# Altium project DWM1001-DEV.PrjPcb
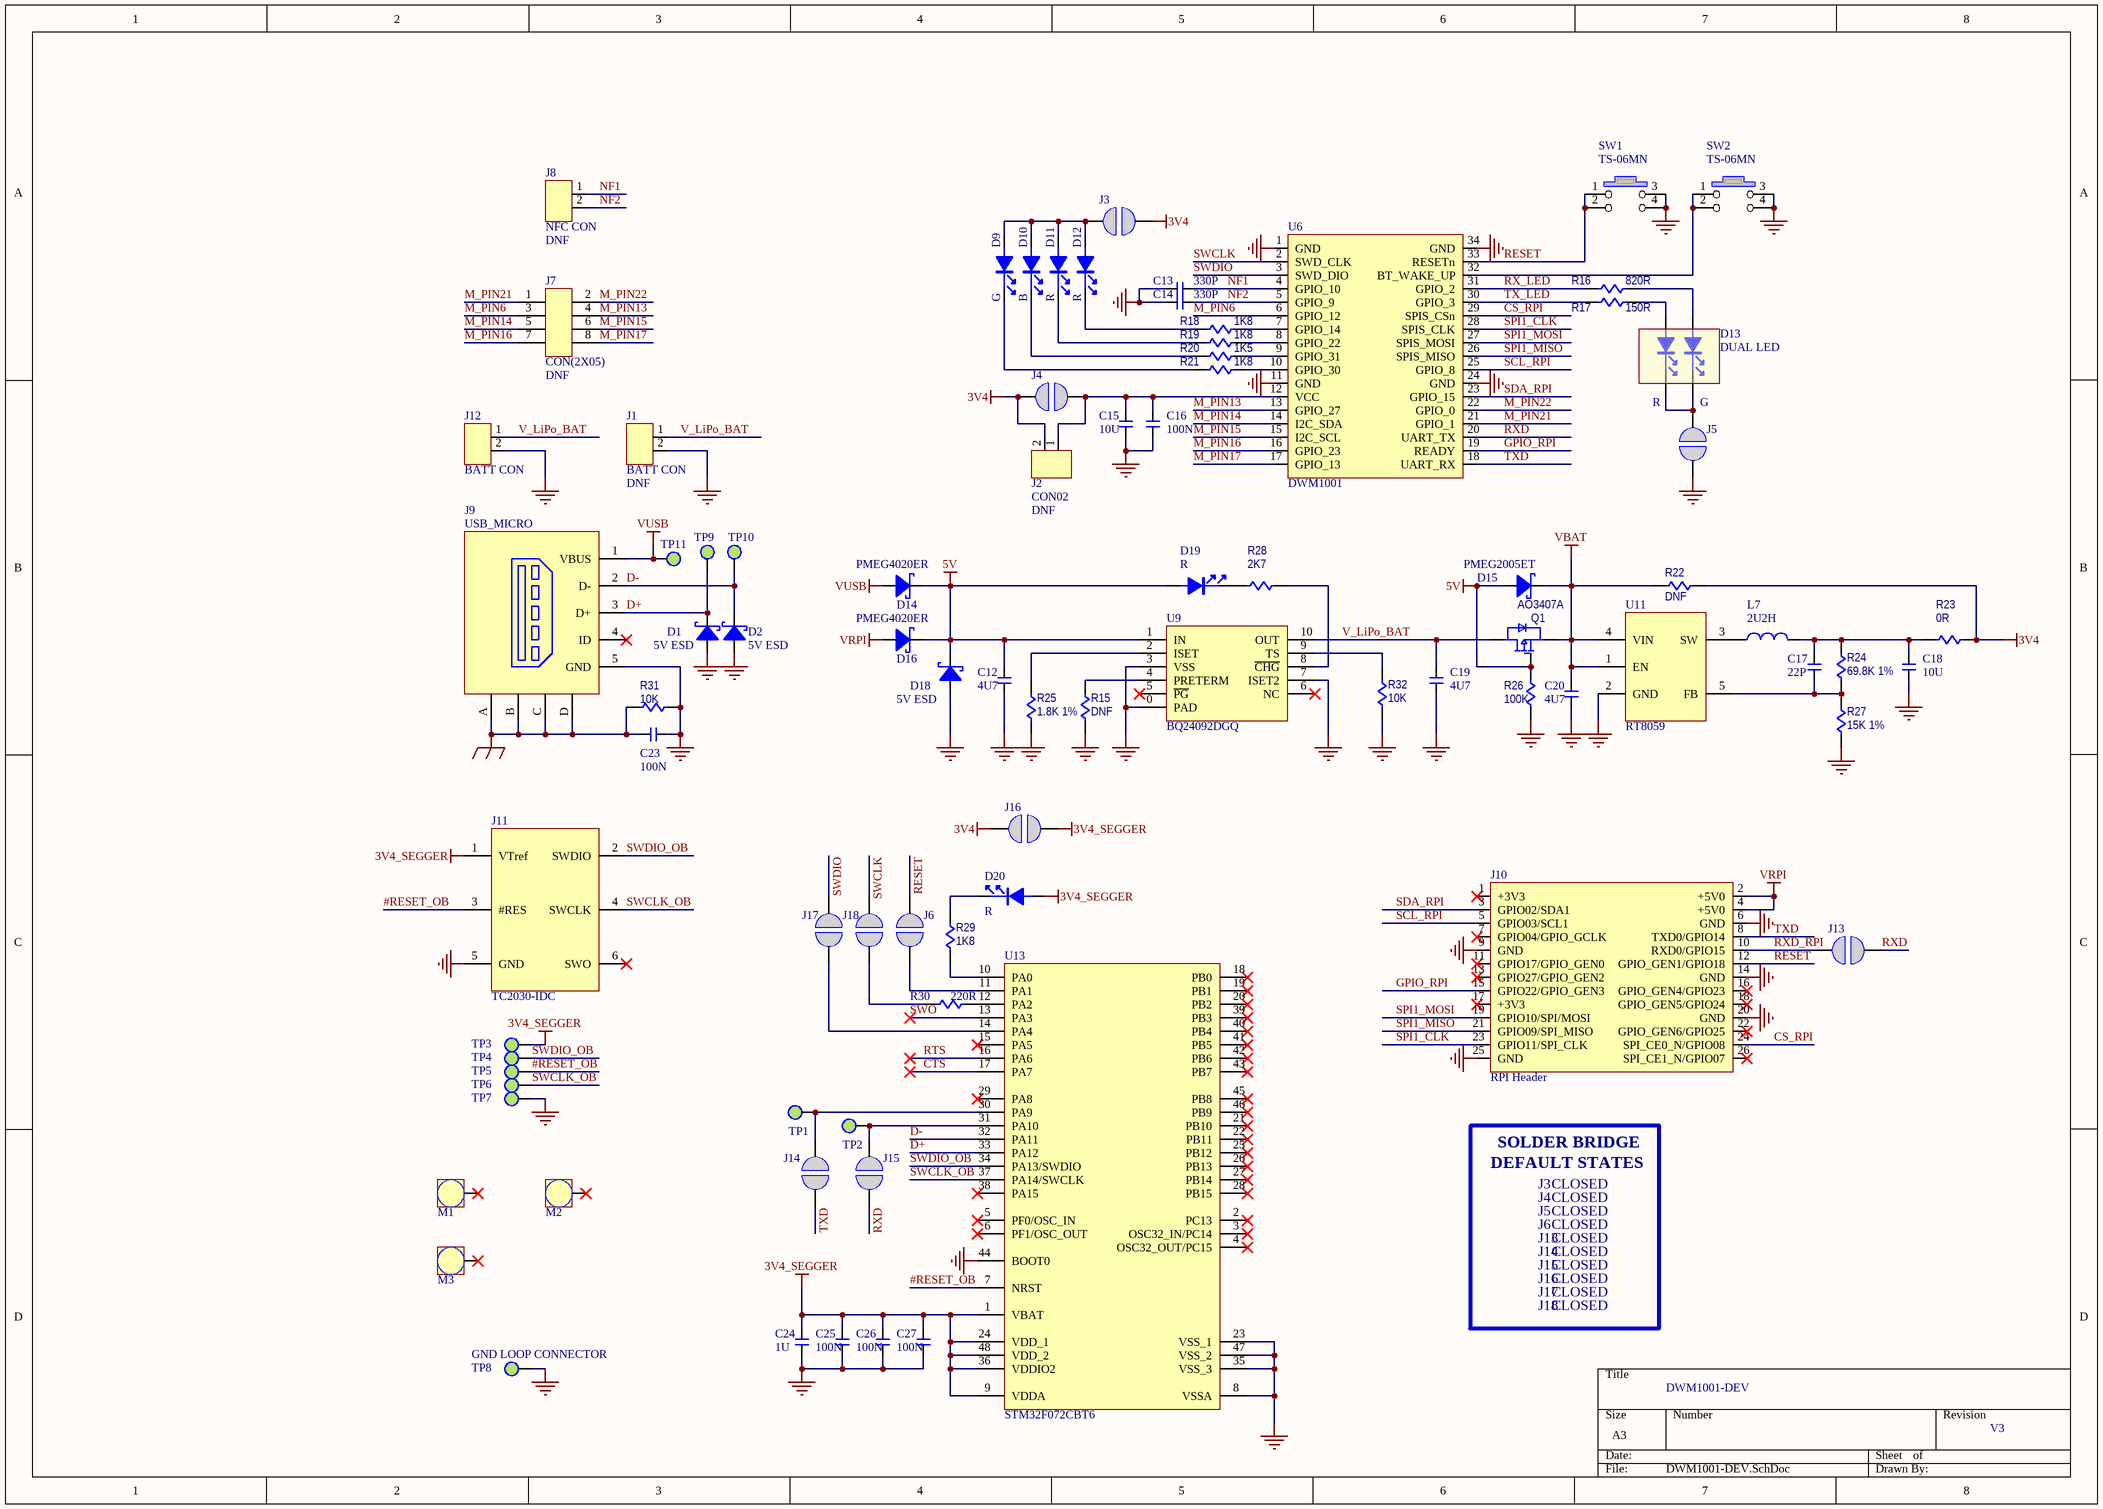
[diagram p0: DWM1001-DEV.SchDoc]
1 sheet, 85 parts. Net scope: global (net labels, ports and power ports of the same name join across sheets).
Board file: DWM1001-DEV.PcbDoc

## Sheet DWM1001-DEV.SchDoc
size A3

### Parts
C12  4U7  [C-SMT-0603]
C13  330P  [C-SMT-0402]
C14  330P  [C-SMT-0402]
C15  10U  [C-SMT-0603]
C16  100N  [C-SMT-0402]
C17  22P  [C-SMT-0402]
C18  10U  [C-SMT-0603]
C19  4U7  [C-SMT-0603]
C20  4U7  [C-SMT-0603]
C23  100N  [C-SMT-0402]
C24  1U  [C-SMT-0402]
C25  100N  [C-SMT-0402]
C26  100N  [C-SMT-0402]
C27  100N  [C-SMT-0402]
D1  5V ESD  [C-SMT-0603]
D2  5V ESD  [C-SMT-0603]
D9  G  [LED-SMT-0603]
D10  B  [LED-SMT-0603]
D11  R  [LED-SMT-0603]
D12  R  [LED-SMT-0603]
D13  DUAL LED  [LED_DUAL]
D14  PMEG4020ER  [DIO_SOD123]
D15  PMEG2005ET  [DIO_SOT23]
D16  PMEG4020ER  [DIO_SOD123]
D18  5V ESD  [C-SMT-0603]
D19  R  [LED-SMT-0603]
D20  R  [LED-SMT-0603]
J1  BATT CON  [CON-100MIL-02]
J2  CON02  [CON-100MIL-02]
J3  SHORT  [PAD_JUMPER]  (value not drawn)
J4  SHORT  [PAD_JUMPER]  (value not drawn)
J5  SHORT  [PAD_JUMPER]  (value not drawn)
J6  SHORT  [PAD_JUMPER]  (value not drawn)
J7  CON(2X05)  [CON-100MIL-2X04]
J8  NFC CON  [CON-100MIL-02]
J9  USB_MICRO  [USB_MICRO_U6F05E-CXT2-B15]
J10  RPI Header  [CON-100MIL-2X13]
J11  TC2030-IDC  [JLINK_6PIN_ADAPTOR]
J12  BATT CON  [SH02AYS]
J13  SHORT  [PAD_JUMPER]  (value not drawn)
J14  SHORT  [PAD_JUMPER]  (value not drawn)
J15  SHORT  [PAD_JUMPER]  (value not drawn)
J16  SHORT  [PAD_JUMPER]  (value not drawn)
J17  SHORT  [PAD_JUMPER]  (value not drawn)
J18  SHORT  [PAD_JUMPER]  (value not drawn)
L7  2U2H  [IND_SDB3015]
M1  mt_hole  [MT_hole_3mm - NPTH]  (value not drawn)
M2  mt_hole  [MT_hole_3mm - NPTH]  (value not drawn)
M3  mt_hole  [MT_hole_3mm - NPTH]  (value not drawn)
Q1  AO3407A  [FET_SOT23_GSD]
R15  DNF  [R-SMT-0402]
R16  820R  [R-SMT-0402]
R17  150R  [R-SMT-0402]
R18  1K8  [R-SMT-0402]
R19  1K8  [R-SMT-0402]
R20  1K5  [R-SMT-0402]
R21  1K8  [R-SMT-0402]
R22  DNF  [R-SMT-0402]
R23  0R  [R-SMT-0402]
R24  69.8K 1%  [R-SMT-0402]
R25  1.8K 1%  [R-SMT-0402]
R26  100K  [R-SMT-0402]
R27  15K 1%  [R-SMT-0402]
R28  2K7  [R-SMT-0402]
R29  1K8  [R-SMT-0402]
R30  220R  [R-SMT-0402]
R31  10K  [R-SMT-0402]
R32  10K  [R-SMT-0402]
SW1  TS-06MN  [TS-1143S]
SW2  TS-06MN  [TS-1143S]
TP1  TXD  [PAD/R40MIL-SMD]  (value not drawn)
TP2  RXD  [PAD/R40MIL-SMD]  (value not drawn)
TP3  3V4_SEGGER  [PAD/R40MIL-SMD]  (value not drawn)
TP4  SWDIO_OB  [PAD/R40MIL-SMD]  (value not drawn)
TP5  #RESET_OB  [PAD/R40MIL-SMD]  (value not drawn)
TP6  SWCLK_OB  [PAD/R40MIL-SMD]  (value not drawn)
TP7  GND  [PAD/R40MIL-SMD]  (value not drawn)
TP8  GND LOOP CONNECTOR  [TP_LOOP_CONNECTOR]
TP9  D+  [PAD/R40MIL-SMD]  (value not drawn)
TP10  D-  [PAD/R40MIL-SMD]  (value not drawn)
TP11  VUSB  [PAD/R40MIL-SMD]  (value not drawn)
U6  DWM1001  [LM1_E1]
U9  BQ24092DGQ  [IC_MSOP10 - TI - DGQ]
U11  RT8059  [SOT23-5]
U13  STM32F072CBT6

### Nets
3V4: J2.2 J3.1 J4.1 J16.1 R22.2 R23.2
3V4_SEGGER: C24.1 C25.1 C26.1 C27.1 D20.A J11.1(VTref) J16.2 TP3.1 U13.1(VBAT) U13.9(VDDA) U13.24(VDD_1) U13.36(VDDIO2) U13.48(VDD_2)
5V: C12.1 D14.2(K) D15.1(A) D16.2(K) D18.2(K) D19.A Q1.G R26.2 U9.1(IN)
EARTH: C23.1 J9.A J9.B J9.C J9.D R31.1
GND: C12.2 C13.1 C14.1 C15.2 C16.2 C18.2 C19.2 C20.2 C23.2 C24.2 C25.2 C26.2 C27.2 D1.1(A) D2.1(A) D18.1(A) J1.2 J5.1 J9.5(GND) J10.6(GND) J10.9(GND) J10.14(GND) J10.20(GND) J10.25(GND) J11.5(GND) J12.2 R15.1 R25.1 R26.1 R27.1 R31.2 R32.1 SW1.3 SW1.4 SW2.3 SW2.4 TP7.1 TP8.1 U6.1(GND) U6.11(GND) U6.24(GND) U6.34(GND) U9.0(PAD) U9.3(VSS) U9.7(ISET2) U11.2(GND) U13.8(VSSA) U13.23(VSS_1) U13.35(VSS_3) U13.44(BOOT0) U13.47(VSS_2)
VBAT: C20.1 D15.2(K) Q1.S R22.1 U11.1(EN) U11.4(VIN)
VRPI: D16.1(A) J10.2(+5V0) J10.4(+5V0)
VUSB: D14.1(A) J9.1(VBUS) TP11.1
#RESET_OB: J11.3(#RES) TP5.1 U13.7(NRST)
CS_RPI: J10.24(SPI_CE0_N/GPIO08) U6.29(SPIS_CSn)
CTS: U13.17(PA7)
D+: D1.2(K) J9.3(D+) TP9.1 U13.33(PA12)
D-: D2.2(K) J9.2(D-) TP10.1 U13.32(PA11)
GPIO_RPI: J10.15(GPIO22/GPIO_GEN3) U6.19(READY)
M_PIN6: J7.3 U6.6(GPIO_12)
M_PIN13: J7.4 U6.13(GPIO_27)
M_PIN14: J7.5 U6.14(I2C_SDA)
M_PIN15: J7.6 U6.15(I2C_SCL)
M_PIN16: J7.7 U6.16(GPIO_23)
M_PIN17: J7.8 U6.17(GPIO_13)
M_PIN21: J7.1 U6.21(GPIO_1)
M_PIN22: J7.2 U6.22(GPIO_0)
NF1: C13.2 J8.1 U6.4(GPIO_10)
NF2: C14.2 J8.2 U6.5(GPIO_9)
RESET: J6.1 J10.12(GPIO_GEN1/GPIO18) SW1.1 SW1.2 U6.33(RESETn)
RTS: U13.16(PA6)
RX_LED: R16.1 U6.31(GPIO_2)
RXD: J13.1 J15.1 U6.20(UART_TX)
RXD_RPI: J10.10(RXD0/GPIO15) J13.2
SCL_RPI: J10.5(GPIO03/SCL1) U6.25(GPIO_8)
SDA_RPI: J10.3(GPIO02/SDA1) U6.23(GPIO_15)
SPI1_CLK: J10.23(GPIO11/SPI_CLK) U6.28(SPIS_CLK)
SPI1_MISO: J10.21(GPIO09/SPI_MISO) U6.26(SPIS_MISO)
SPI1_MOSI: J10.19(GPIO10/SPI/MOSI) U6.27(SPIS_MOSI)
SWCLK: J18.1 U6.2(SWD_CLK)
SWCLK_OB: J11.4(SWCLK) TP6.1 U13.37(PA14/SWCLK)
SWDIO: J17.1 U6.3(SWD_DIO)
SWDIO_OB: J11.2(SWDIO) TP4.1 U13.34(PA13/SWDIO)
SWO: U13.13(PA3)
TX_LED: R17.1 U6.30(GPIO_3)
TXD: J10.8(TXD0/GPIO14) J14.1 U6.18(UART_RX)
V_LiPo_BAT: C19.1 J1.1 J12.1 Q1.D U9.10(OUT)
NetC15_1: C15.1 C16.1 J2.1 J4.2 U6.12(VCC)
NetC17_1: C17.1 C18.1 L7.2 R23.1 R24.2
NetC17_2: C17.2 R24.1 R27.2 U11.5(FB)
NetD9_A: D9.A D10.A D11.A D12.A J3.2
NetD9_K: D9.K R21.1
NetD10_K: D10.K R20.1
NetD11_K: D11.K R19.1
NetD12_K: D12.K R18.1
NetD13_1: D13.1(A1) R16.2
NetD13_2: D13.2(K1) D13.4(K2) J5.2
NetD13_3: D13.3(A2) R17.2
NetD19_K: D19.K R28.1
NetD20_K: D20.K R29.2
NetJ6_2: J6.2 U13.11(PA1)
NetJ14_2: J14.2 TP1.1 U13.30(PA9)
NetJ15_2: J15.2 TP2.1 U13.31(PA10)
NetJ17_2: J17.2 U13.14(PA4)
NetJ18_2: J18.2 R30.1
NetL7_1: L7.1 U11.3(SW)
NetR15_2: R15.2 U9.4(PRETERM)
NetR18_2: R18.2 U6.7(GPIO_14)
NetR19_2: R19.2 U6.8(GPIO_22)
NetR20_2: R20.2 U6.9(GPIO_31)
NetR21_2: R21.2 U6.10(GPIO_30)
NetR25_2: R25.2 U9.2(ISET)
NetR28_2: R28.2 U9.8(~{CHG})
NetR29_1: R29.1 U13.10(PA0)
NetR30_2: R30.2 U13.12(PA2)
NetR32_2: R32.2 U9.9(TS)
NetSW2_1: SW2.1 SW2.2 U6.32(BT_WAKE_UP)

Not connected (* = marked no-connect by the designer): J9 4(ID)*; J10 1(+3V3)* 7(GPIO04/GPIO_GCLK)* 11(GPIO17/GPIO_GEN0)* 13(GPIO27/GPIO_GEN2)* 16(GPIO_GEN4/GPIO23)* 17(+3V3)* 18(GPIO_GEN5/GPIO24)* 22(GPIO_GEN6/GPIO25)* 26(SPI_CE1_N/GPIO07)*; J11 6(SWO)*; M1 1(GND)*; M2 1(GND)*; M3 1(GND)*; U9 5(~{PG})* 6(NC)*; U13 2(PC13)* 3(OSC32_IN/PC14)* 4(OSC32_OUT/PC15)* 5(PF0/OSC_IN)* 6(PF1/OSC_OUT)* 15(PA5)* 18(PB0)* 19(PB1)* 20(PB2)* 21(PB10)* 22(PB11)* 25(PB12)* 26(PB13)* 27(PB14)* 28(PB15)* 29(PA8)* 38(PA15)* 39(PB3)* 40(PB4)* 41(PB5)* 42(PB6)* 43(PB7)* 45(PB8)* 46(PB9)*

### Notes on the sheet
- R
- G
- DEFAULT STATES
- SOLDER BRIDGE
- J3
- CLOSED
- J5
- J13
- J14
- J4
- J6
- J15
- J16
- J17
- J18
- DWM1001-DEV
- V3

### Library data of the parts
C12-C20 C23-C27 = C-SMT-0402: *C-SMT-0402
D1 D2 D14-D16 D18 = DIODE_SCHOTTKY: Diode
D9-D12 D19 D20 = LED
D13 = LED_X2
J1 J2 J8 J12 = CON02: 2 pin Connector
J3-J6 J13-J18 = JUMPER_OPEN
J7 = CON(2X04)_1
J9 = CON05_USB_2: USB-MR1-05-TH-MB
J10 = RPI_HEADER_SHORT
J11 = TC2030-IDC: J-Link 6-pin Programming Pads
L7 = L: INDUCTOR
Q1 = MOSFET-P1: P-MOSFET
R15-R32 = R-SMT-0402: *R-SMT-0402; Value: 500R
SW1 SW2 = TACT_SW/4PIN
TP1-TP11 = TEST POINT_1: TEST POINT
U6 = LM1_E1
U13 = STM32F072CxU6: J-LINK MCU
